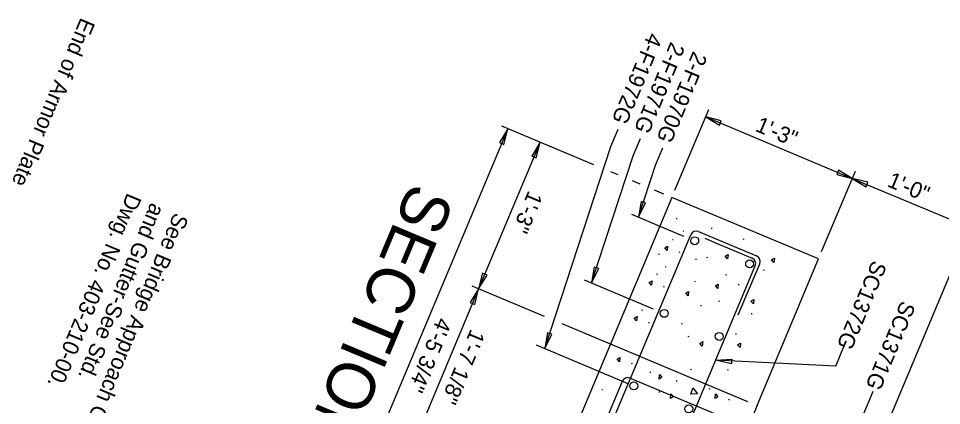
# Model space of a CAD drawing. Extents: x 1968564 to 1968711, y 796599 to 796794.
# Drawn here: x 1968616.17 to 1968645.19, y 796702.14 to 796714.31 of the extents above; entities that cross this region are included whole.
import ezdxf

# ---------------------------------------------------------------- set-up
doc = ezdxf.new("R2010")
doc.units = 0
for name, color, linetype in [('BR_AUTO DIMENSION', 7, 'Continuous'), ('BR_CONCRETE', 7, 'Continuous'), ('BR_DETAILS', 7, 'Continuous'), ('BR_REBAR', 7, 'Continuous'), ('BR_TEXT', 7, 'Continuous')]:
    doc.layers.add(name, color=color, linetype=linetype)

msp = doc.modelspace()

# ---------------------------------------------------------------- linework, layer by layer
at = {"layer": 'BR_AUTO DIMENSION'}
for p, q in [((1968636.813, 796708.912), (1968637.876, 796711.446)), ((1968637.779, 796711.216), (1968642.39, 796709.282)), ((1968631.561, 796710.844), (1968625.759, 796697.011)), ((1968634.266, 796709.709), (1968631.368, 796710.924)), ((1968634.795, 796710.286), (1968635.024, 796710.831)), ((1968635.497, 796709.992), (1968635.726, 796710.537)), ((1968632.575, 796710.418), (1968630.641, 796705.807)), ((1968632.718, 796703.929), (1968634.795, 796710.286)), ((1968636.2, 796709.697), (1968636.428, 796710.242)), ((1968634.192, 796705.995), (1968635.497, 796709.992)), ((1968635.665, 796708.06), (1968636.2, 796709.697)), ((1968635.024, 796709.391), (1968634.795, 796709.487)), ((1968641.424, 796706.978), (1968642.487, 796709.512)), ((1968641.424, 796706.978), (1968642.487, 796709.512)), ((1968635.719, 796709.1), (1968635.474, 796709.202)), ((1968642.39, 796709.282), (1968646.079, 796707.735)), ((1968636.461, 796708.788), (1968636.171, 796708.91)), ((1968635.444, 796708.153), (1968637.086, 796707.464)), ((1968643.179, 796700.82), (1968646.176, 796707.965)), ((1968632.708, 796704.941), (1968630.442, 796705.891)), ((1968633.963, 796706.091), (1968636.129, 796705.182)), ((1968630.641, 796705.807), (1968628.707, 796701.196)), ((1968639.108, 796702.256), (1968633.268, 796704.705)), ((1968632.446, 796704.044), (1968635.33, 796702.834)), ((1968641.868, 796703.376), (1968642.147, 796704.043)), ((1968641.868, 796703.376), (1968638.093, 796703.561)), ((1968642.763, 796701.908), (1968643.048, 796702.588))]:
    msp.add_line(p, q, dxfattribs=at)
for points in [[(1968638.27, 796711.091), (1968637.779, 796711.216), (1968638.212, 796710.953)], [(1968631.437, 796710.353), (1968631.561, 796710.844), (1968631.298, 796710.411)], [(1968632.451, 796709.928), (1968632.575, 796710.418), (1968632.313, 796709.986)], [(1968641.9, 796709.406), (1968642.39, 796709.282), (1968641.958, 796709.544)], [(1968642.88, 796709.158), (1968642.39, 796709.282), (1968642.822, 796709.019)], [(1968635.749, 796708.559), (1968635.665, 796708.06), (1968635.891, 796708.512)], [(1968634.276, 796706.493), (1968634.192, 796705.995), (1968634.418, 796706.447)], [(1968630.765, 796706.297), (1968630.641, 796705.807), (1968630.904, 796706.239)], [(1968630.517, 796705.317), (1968630.641, 796705.807), (1968630.379, 796705.375)], [(1968632.802, 796704.428), (1968632.718, 796703.929), (1968632.945, 796704.381)], [(1968638.586, 796703.448), (1968638.093, 796703.561), (1968638.598, 796703.598)]]:
    msp.add_lwpolyline(points, close=True, dxfattribs=at)
at = {"layer": 'BR_CONCRETE'}
for p, q in [((1968636.716, 796708.681), (1968630.915, 796694.849)), ((1968641.327, 796706.747), (1968636.716, 796708.681)), ((1968639.393, 796702.136), (1968641.327, 796706.747)), ((1968639.393, 796702.136), (1968638.749, 796700.6))]:
    msp.add_line(p, q, dxfattribs=at)
at = {"layer": 'BR_DETAILS'}
for p, q in [((1968636.853, 796708.019), (1968636.883, 796708.025)), ((1968637.067, 796707.623), (1968637.096, 796707.629)), ((1968637.955, 796707.714), (1968637.984, 796707.72)), ((1968636.733, 796707.359), (1968636.762, 796707.364)), ((1968638.956, 796707.371), (1968638.985, 796707.377)), ((1968636.297, 796706.899), (1968636.326, 796706.905)), ((1968636.946, 796706.963), (1968636.976, 796706.969)), ((1968637.46, 796706.736), (1968637.49, 796706.741)), ((1968637.817, 796706.794), (1968637.846, 796706.799)), ((1968636.511, 796706.504), (1968636.54, 796706.51)), ((1968636.244, 796706.269), (1968636.273, 796706.275)), ((1968638.413, 796706.253), (1968638.443, 796706.259)), ((1968639.602, 796706.4), (1968639.632, 796706.405)), ((1968636.457, 796705.873), (1968636.487, 796705.879)), ((1968637.434, 796706.039), (1968637.464, 796706.044)), ((1968638.805, 796705.944), (1968638.834, 796705.949)), ((1968637.615, 796705.28), (1968637.645, 796705.286)), ((1968638.192, 796705.423), (1968638.221, 796705.429)), ((1968635.771, 796705.142), (1968635.801, 796705.148)), ((1968639.209, 796705.031), (1968639.239, 796705.036)), ((1968635.985, 796704.747), (1968636.014, 796704.753)), ((1968637.016, 796704.708), (1968637.046, 796704.714)), ((1968637.23, 796704.312), (1968637.259, 796704.318)), ((1968638.714, 796704.388), (1968638.744, 796704.394)), ((1968635.447, 796703.464), (1968635.476, 796703.469)), ((1968637.299, 796703.271), (1968637.328, 796703.277)), ((1968638.467, 796703.261), (1968638.496, 796703.266)), ((1968636.022, 796703.183), (1968636.051, 796703.189)), ((1968636.847, 796702.922), (1968636.876, 796702.892)), ((1968634.509, 796702.638), (1968634.539, 796702.644)), ((1968636.301, 796702.575), (1968636.329, 796702.545)), ((1968637.912, 796702.662), (1968637.882, 796702.656)), ((1968638.496, 796702.34), (1968638.524, 796702.31))]:
    msp.add_line(p, q, dxfattribs=at)
for points in [[(1968636.568, 796707.013), (1968636.492, 796707.099), (1968636.582, 796707.152), (1968636.568, 796707.013)], [(1968638.469, 796706.75), (1968638.393, 796706.836), (1968638.482, 796706.889), (1968638.469, 796706.75)], [(1968639.926, 796706.632), (1968639.849, 796706.719), (1968639.939, 796706.771), (1968639.926, 796706.632)], [(1968636.08, 796705.923), (1968636.003, 796706.01), (1968636.093, 796706.062), (1968636.08, 796705.923)], [(1968638.162, 796705.815), (1968638.086, 796705.901), (1968638.175, 796705.954), (1968638.162, 796705.815)], [(1968637.228, 796705.586), (1968637.151, 796705.672), (1968637.241, 796705.725), (1968637.228, 796705.586)], [(1968639.28, 796705.338), (1968639.204, 796705.424), (1968639.293, 796705.476), (1968639.28, 796705.338)], [(1968635.607, 796704.797), (1968635.531, 796704.883), (1968635.621, 796704.936), (1968635.607, 796704.797)], [(1968637.673, 796704.007), (1968637.597, 796704.093), (1968637.687, 796704.146), (1968637.673, 796704.007)], [(1968638.859, 796703.958), (1968638.782, 796704.044), (1968638.872, 796704.097), (1968638.859, 796703.958)], [(1968635.069, 796703.514), (1968634.992, 796703.6), (1968635.082, 796703.652), (1968635.069, 796703.514)], [(1968636.326, 796703.11), (1968636.403, 796703.024), (1968636.313, 796702.971), (1968636.326, 796703.11)], [(1968637.373, 796702.689), (1968637.526, 796702.504), (1968637.311, 796702.499), (1968637.372, 796702.685)], [(1968636.688, 796702.502), (1968636.764, 796702.416), (1968636.675, 796702.363), (1968636.688, 796702.502)], [(1968638.09, 796702.502), (1968638.166, 796702.415), (1968638.076, 796702.363), (1968638.09, 796702.502)]]:
    msp.add_lwpolyline(points, dxfattribs=at)
at = {"layer": 'BR_REBAR'}
for p, q in [((1968632.167, 796695.249), (1968637.308, 796707.506)), ((1968637.554, 796707.607), (1968639.379, 796706.841)), ((1968637.756, 796707.398), (1968638.217, 796707.204)), ((1968638.217, 796707.204), (1968639.238, 796706.776)), ((1968634.242, 796694.379), (1968639.339, 796706.531)), ((1968638.804, 796704.986), (1968639.479, 796706.596)), ((1968641.928, 796700.26), (1968635.399, 796702.999)), ((1968635.153, 796702.898), (1968633.99, 796700.125))]:
    msp.add_line(p, q, dxfattribs=at)
for centre in [(1968637.433, 796707.319), (1968639.162, 796706.594), (1968636.476, 796705.037), (1968638.205, 796704.312), (1968635.519, 796702.755), (1968637.248, 796702.03)]:
    msp.add_circle(centre, 0.125, dxfattribs=at)
for centre, start, end in [((1968637.481, 796707.434), 67.246, 157.246), ((1968639.166, 796706.603), 337.246, 67.246), ((1968639.306, 796706.668), 337.246, 67.246), ((1968635.326, 796702.826), 67.246, 157.246)]:
    msp.add_arc(centre, 0.188, start, end, dxfattribs=at)

# ---------------------------------------------------------------- texts
at = {"layer": 'BR_AUTO DIMENSION'}
for s, rotation, p in [('1\'-3"', 337.246, (1968639.308, 796710.783)), ('1\'-0"', 337.246, (1968643.458, 796709.043)), ('1\'-3"', 247.246, (1968632.211, 796708.923)), ('4\'-5 3/4"', 247.246, (1968629.35, 796704.94)), ('1\'-7 1/8"', 247.246, (1968630.396, 796704.569))]:
    msp.add_text(s, height=0.5, rotation=rotation, dxfattribs=at).set_placement(p)
at = {"layer": 'BR_TEXT'}
for s, height, p in [('End of Armor Plate', 0.49995, (1968618.134, 796714.364)), ('4-F1972G', 0.4999, (1968635.98, 796713.895)), ('2-F1971G', 0.4999, (1968636.682, 796713.601)), ('2-F1970G', 0.4999, (1968637.385, 796713.306)), ('SECTION F-F', 1.5, (1968628.519, 796709.209)), ('Dwg. No. 403-210-00.', 0.49995, (1968619.597, 796708.85)), ('and Gutter-See Std.', 0.49995, (1968620.334, 796708.541)), ('See Bridge Approach Curb', 0.49995, (1968621.072, 796708.231)), ('SC1372G', 0.4999, (1968643.029, 796706.733)), (' SC1371G', 0.4999, (1968644.003, 796705.633))]:
    msp.add_text(s, height=height, rotation=247.246, dxfattribs=at).set_placement(p)

doc.saveas('drawing.dxf')
